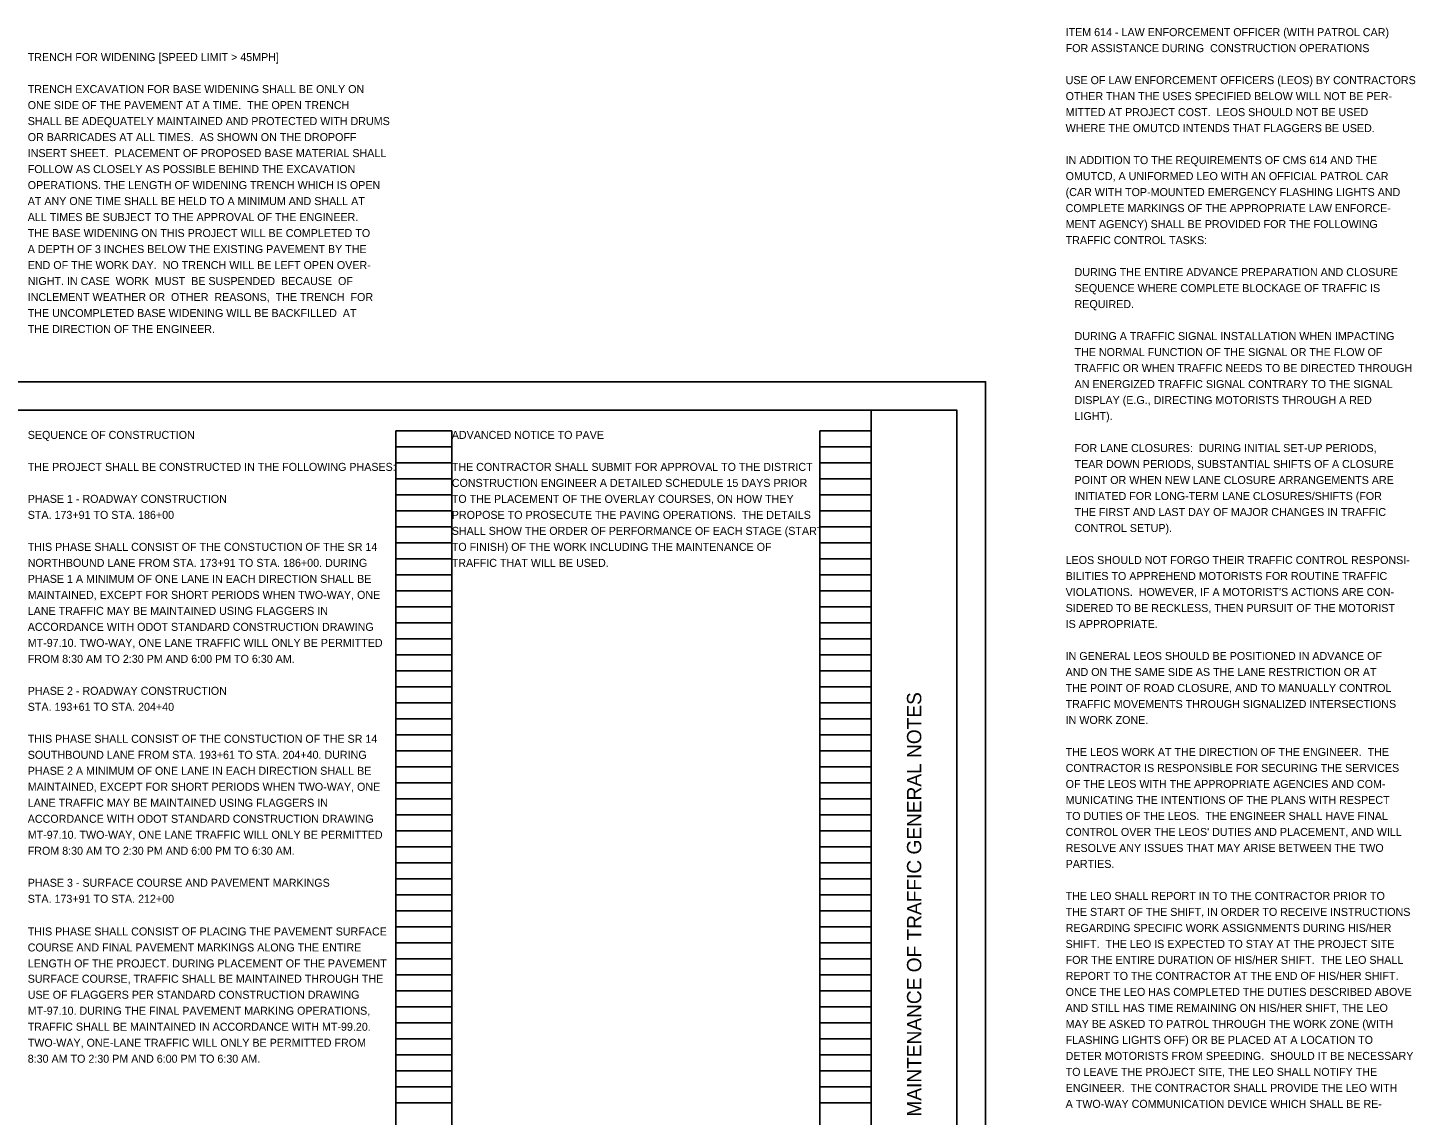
# Model space of a CAD drawing. Extents: x -7.4 to 41.7, y -6.6 to 28.2.
# Drawn here: x 17.24 to 41.52, y 9.16 to 28.2 of the extents above; entities that cross this region are included whole.
import ezdxf

# ---------------------------------------------------------------- set-up
doc = ezdxf.new("R2010")
doc.units = 0
for name, color, linetype in [('SH_Border', 7, 'Continuous'), ('SH_Cut_Line', 7, 'Continuous'), ('SH_Data', 7, 'Continuous'), ('SH_Text', 7, 'Continuous')]:
    doc.layers.add(name, color=color, linetype=linetype)

msp = doc.modelspace()

# ---------------------------------------------------------------- linework, layer by layer
at = {"layer": 'SH_Border'}
msp.add_line((32, 0.5), (32, 21.5), dxfattribs=at)
msp.add_lwpolyline([(1.5, 21.5), (33.5, 21.5), (33.5, 0.5), (1.5, 0.5)], close=True, dxfattribs=at)
at = {"layer": 'SH_Cut_Line'}
msp.add_lwpolyline([(0, 0), (34, 0), (34, 22), (0, 22)], close=True, dxfattribs=at)
at = {"layer": 'SH_Data'}
for p, q in [((23.68, 0.98), (23.68, 21.14)), ((23.68, 21.14), (24.66, 21.14)), ((24.66, 0.98), (24.66, 21.14)), ((31.1, 0.98), (31.1, 21.14)), ((31.1, 21.14), (32, 21.14)), ((32, 0.98), (32, 21.14)), ((23.68, 20.86), (24.66, 20.86)), ((31.1, 20.86), (32, 20.86)), ((23.68, 20.58), (24.66, 20.58)), ((31.1, 20.58), (32, 20.58)), ((23.68, 20.3), (24.66, 20.3)), ((31.1, 20.3), (32, 20.3)), ((23.68, 20.02), (24.66, 20.02)), ((31.1, 20.02), (32, 20.02)), ((23.68, 19.74), (24.66, 19.74)), ((31.1, 19.74), (32, 19.74)), ((23.68, 19.46), (24.66, 19.46)), ((31.1, 19.46), (32, 19.46)), ((23.68, 19.18), (24.66, 19.18)), ((31.1, 19.18), (32, 19.18)), ((23.68, 18.9), (24.66, 18.9)), ((31.1, 18.9), (32, 18.9)), ((23.68, 18.62), (24.66, 18.62)), ((31.1, 18.62), (32, 18.62)), ((23.68, 18.34), (24.66, 18.34)), ((31.1, 18.34), (32, 18.34)), ((23.68, 18.06), (24.66, 18.06)), ((31.1, 18.06), (32, 18.06)), ((23.68, 17.78), (24.66, 17.78)), ((31.1, 17.78), (32, 17.78)), ((23.68, 17.5), (24.66, 17.5)), ((31.1, 17.5), (32, 17.5)), ((23.68, 17.22), (24.66, 17.22)), ((31.1, 17.22), (32, 17.22)), ((23.68, 16.94), (24.66, 16.94)), ((31.1, 16.94), (32, 16.94)), ((23.68, 16.66), (24.66, 16.66)), ((31.1, 16.66), (32, 16.66)), ((23.68, 16.38), (24.66, 16.38)), ((31.1, 16.38), (32, 16.38)), ((23.68, 16.1), (24.66, 16.1)), ((31.1, 16.1), (32, 16.1)), ((23.68, 15.82), (24.66, 15.82)), ((31.1, 15.82), (32, 15.82)), ((23.68, 15.54), (24.66, 15.54)), ((31.1, 15.54), (32, 15.54)), ((23.68, 15.26), (24.66, 15.26)), ((31.1, 15.26), (32, 15.26)), ((23.68, 14.98), (24.66, 14.98)), ((31.1, 14.98), (32, 14.98)), ((23.68, 14.7), (24.66, 14.7)), ((31.1, 14.7), (32, 14.7)), ((23.68, 14.42), (24.66, 14.42)), ((31.1, 14.42), (32, 14.42)), ((23.68, 14.14), (24.66, 14.14)), ((31.1, 14.14), (32, 14.14)), ((23.68, 13.86), (24.66, 13.86)), ((31.1, 13.86), (32, 13.86)), ((23.68, 13.58), (24.66, 13.58)), ((31.1, 13.58), (32, 13.58)), ((23.68, 13.3), (24.66, 13.3)), ((31.1, 13.3), (32, 13.3)), ((23.68, 13.02), (24.66, 13.02)), ((31.1, 13.02), (32, 13.02)), ((23.68, 12.74), (24.66, 12.74)), ((31.1, 12.74), (32, 12.74)), ((23.68, 12.46), (24.66, 12.46)), ((31.1, 12.46), (32, 12.46)), ((23.68, 12.18), (24.66, 12.18)), ((31.1, 12.18), (32, 12.18)), ((23.68, 11.9), (24.66, 11.9)), ((31.1, 11.9), (32, 11.9)), ((23.68, 11.62), (24.66, 11.62)), ((31.1, 11.62), (32, 11.62)), ((23.68, 11.34), (24.66, 11.34)), ((31.1, 11.34), (32, 11.34)), ((23.68, 11.06), (24.66, 11.06)), ((31.1, 11.06), (32, 11.06)), ((23.68, 10.78), (24.66, 10.78)), ((31.1, 10.78), (32, 10.78)), ((23.68, 10.5), (24.66, 10.5)), ((31.1, 10.5), (32, 10.5)), ((23.68, 10.22), (24.66, 10.22)), ((31.1, 10.22), (32, 10.22)), ((23.68, 9.94), (24.66, 9.94)), ((31.1, 9.94), (32, 9.94)), ((23.68, 9.66), (24.66, 9.66)), ((31.1, 9.66), (32, 9.66)), ((23.68, 9.38), (24.66, 9.38)), ((31.1, 9.38), (32, 9.38))]:
    msp.add_line(p, q, dxfattribs=at)

# ---------------------------------------------------------------- texts
msp.add_text('MAINTENANCE OF TRAFFIC GENERAL NOTES', height=0.25, rotation=90, dxfattribs=at).set_placement((32.875, 9.137))
at = {"layer": 'SH_Text'}
for s, p in [('ITEM 614 - LAW ENFORCEMENT OFFICER (WITH PATROL CAR)', (35.401, 28.05)), ('TRENCH FOR WIDENING [SPEED LIMIT > 45MPH]', (17.24, 27.613)), ('FOR ASSISTANCE DURING  CONSTRUCTION OPERATIONS', (35.401, 27.77)), ('TRENCH EXCAVATION FOR BASE WIDENING SHALL BE ONLY ON', (17.24, 27.053)), ('USE OF LAW ENFORCEMENT OFFICERS (LEOS) BY CONTRACTORS', (35.401, 27.21)), ('OTHER THAN THE USES SPECIFIED BELOW WILL NOT BE PER-', (35.401, 26.93)), ('ONE SIDE OF THE PAVEMENT AT A TIME.  THE OPEN TRENCH', (17.24, 26.773)), ('MITTED AT PROJECT COST.  LEOS SHOULD NOT BE USED', (35.401, 26.65)), ('SHALL BE ADEQUATELY MAINTAINED AND PROTECTED WITH DRUMS', (17.24, 26.493)), ('WHERE THE OMUTCD INTENDS THAT FLAGGERS BE USED.', (35.401, 26.37)), ('OR BARRICADES AT ALL TIMES.  AS SHOWN ON THE DROPOFF', (17.24, 26.213)), ('INSERT SHEET.  PLACEMENT OF PROPOSED BASE MATERIAL SHALL', (17.24, 25.933)), ('FOLLOW AS CLOSELY AS POSSIBLE BEHIND THE EXCAVATION', (17.24, 25.653)), ('IN ADDITION TO THE REQUIREMENTS OF CMS 614 AND THE', (35.401, 25.81)), ('OPERATIONS. THE LENGTH OF WIDENING TRENCH WHICH IS OPEN', (17.24, 25.373)), ('OMUTCD, A UNIFORMED LEO WITH AN OFFICIAL PATROL CAR', (35.401, 25.53)), ('(CAR WITH TOP-MOUNTED EMERGENCY FLASHING LIGHTS AND', (35.401, 25.25)), ('AT ANY ONE TIME SHALL BE HELD TO A MINIMUM AND SHALL AT', (17.24, 25.093)), ('COMPLETE MARKINGS OF THE APPROPRIATE LAW ENFORCE-', (35.401, 24.97)), ('ALL TIMES BE SUBJECT TO THE APPROVAL OF THE ENGINEER.', (17.24, 24.813)), ('MENT AGENCY) SHALL BE PROVIDED FOR THE FOLLOWING', (35.401, 24.69)), ('THE BASE WIDENING ON THIS PROJECT WILL BE COMPLETED TO', (17.24, 24.533)), ('TRAFFIC CONTROL TASKS:', (35.401, 24.41)), ('A DEPTH OF 3 INCHES BELOW THE EXISTING PAVEMENT BY THE', (17.24, 24.253)), ('END OF THE WORK DAY.  NO TRENCH WILL BE LEFT OPEN OVER-', (17.24, 23.973)), ('NIGHT. IN CASE  WORK  MUST  BE SUSPENDED  BECAUSE  OF', (17.24, 23.693)), ('   DURING THE ENTIRE ADVANCE PREPARATION AND CLOSURE', (35.401, 23.85)), ('INCLEMENT WEATHER OR  OTHER  REASONS,  THE TRENCH  FOR', (17.24, 23.413)), ('   SEQUENCE WHERE COMPLETE BLOCKAGE OF TRAFFIC IS', (35.401, 23.57)), ('   REQUIRED.', (35.401, 23.29)), ('THE UNCOMPLETED BASE WIDENING WILL BE BACKFILLED  AT', (17.24, 23.133)), ('THE DIRECTION OF THE ENGINEER.', (17.24, 22.853)), ('   DURING A TRAFFIC SIGNAL INSTALLATION WHEN IMPACTING', (35.401, 22.73)), ('   THE NORMAL FUNCTION OF THE SIGNAL OR THE FLOW OF', (35.401, 22.45)), ('   TRAFFIC OR WHEN TRAFFIC NEEDS TO BE DIRECTED THROUGH', (35.401, 22.17)), ('   AN ENERGIZED TRAFFIC SIGNAL CONTRARY TO THE SIGNAL', (35.401, 21.89)), ('   DISPLAY (E.G., DIRECTING MOTORISTS THROUGH A RED', (35.401, 21.61)), ('   LIGHT).', (35.401, 21.33)), ('SEQUENCE OF CONSTRUCTION', (17.24, 21)), ('ADVANCED NOTICE TO PAVE', (24.66, 21)), ('   FOR LANE CLOSURES:  DURING INITIAL SET-UP PERIODS,', (35.401, 20.77)), ('THE PROJECT SHALL BE CONSTRUCTED IN THE FOLLOWING PHASES:', (17.24, 20.44)), ('THE CONTRACTOR SHALL SUBMIT FOR APPROVAL TO THE DISTRICT', (24.66, 20.44)), ('   TEAR DOWN PERIODS, SUBSTANTIAL SHIFTS OF A CLOSURE', (35.401, 20.49)), ('CONSTRUCTION ENGINEER A DETAILED SCHEDULE 15 DAYS PRIOR', (24.66, 20.16)), ('   POINT OR WHEN NEW LANE CLOSURE ARRANGEMENTS ARE', (35.401, 20.21)), ('PHASE 1 - ROADWAY CONSTRUCTION', (17.24, 19.88)), ('TO THE PLACEMENT OF THE OVERLAY COURSES, ON HOW THEY', (24.66, 19.88)), ('   INITIATED FOR LONG-TERM LANE CLOSURES/SHIFTS (FOR', (35.401, 19.93)), ('STA. 173+91 TO STA. 186+00', (17.24, 19.6)), ('PROPOSE TO PROSECUTE THE PAVING OPERATIONS.  THE DETAILS', (24.66, 19.6)), ('   THE FIRST AND LAST DAY OF MAJOR CHANGES IN TRAFFIC', (35.401, 19.65)), ('SHALL SHOW THE ORDER OF PERFORMANCE OF EACH STAGE (START', (24.66, 19.32)), ('   CONTROL SETUP).', (35.401, 19.37)), ('THIS PHASE SHALL CONSIST OF THE CONSTUCTION OF THE SR 14', (17.24, 19.04)), ('TO FINISH) OF THE WORK INCLUDING THE MAINTENANCE OF', (24.66, 19.04)), ('LEOS SHOULD NOT FORGO THEIR TRAFFIC CONTROL RESPONSI-', (35.401, 18.81)), ('NORTHBOUND LANE FROM STA. 173+91 TO STA. 186+00. DURING', (17.24, 18.76)), ('TRAFFIC THAT WILL BE USED.', (24.66, 18.76)), ('PHASE 1 A MINIMUM OF ONE LANE IN EACH DIRECTION SHALL BE ', (17.24, 18.48)), ('BILITIES TO APPREHEND MOTORISTS FOR ROUTINE TRAFFIC', (35.401, 18.53)), ('MAINTAINED, EXCEPT FOR SHORT PERIODS WHEN TWO-WAY, ONE', (17.24, 18.2)), ("VIOLATIONS.  HOWEVER, IF A MOTORIST'S ACTIONS ARE CON-", (35.401, 18.25)), ('LANE TRAFFIC MAY BE MAINTAINED USING FLAGGERS IN ', (17.24, 17.92)), ('SIDERED TO BE RECKLESS, THEN PURSUIT OF THE MOTORIST', (35.401, 17.97)), ('ACCORDANCE WITH ODOT STANDARD CONSTRUCTION DRAWING ', (17.24, 17.64)), ('IS APPROPRIATE.', (35.401, 17.69)), ('MT-97.10. TWO-WAY, ONE LANE TRAFFIC WILL ONLY BE PERMITTED', (17.24, 17.36)), ('IN GENERAL LEOS SHOULD BE POSITIONED IN ADVANCE OF', (35.401, 17.13)), ('FROM 8:30 AM TO 2:30 PM AND 6:00 PM TO 6:30 AM. ', (17.24, 17.08)), ('AND ON THE SAME SIDE AS THE LANE RESTRICTION OR AT', (35.401, 16.85)), ('PHASE 2 - ROADWAY CONSTRUCTION', (17.24, 16.52)), ('THE POINT OF ROAD CLOSURE, AND TO MANUALLY CONTROL', (35.401, 16.57)), ('STA. 193+61 TO STA. 204+40', (17.24, 16.24)), ('TRAFFIC MOVEMENTS THROUGH SIGNALIZED INTERSECTIONS', (35.401, 16.29)), ('IN WORK ZONE.', (35.401, 16.01)), ('THIS PHASE SHALL CONSIST OF THE CONSTUCTION OF THE SR 14', (17.24, 15.68)), ('SOUTHBOUND LANE FROM STA. 193+61 TO STA. 204+40. DURING', (17.24, 15.4)), ('THE LEOS WORK AT THE DIRECTION OF THE ENGINEER.  THE', (35.401, 15.45)), ('CONTRACTOR IS RESPONSIBLE FOR SECURING THE SERVICES', (35.401, 15.17)), ('PHASE 2 A MINIMUM OF ONE LANE IN EACH DIRECTION SHALL BE ', (17.24, 15.12)), ('MAINTAINED, EXCEPT FOR SHORT PERIODS WHEN TWO-WAY, ONE', (17.24, 14.84)), ('OF THE LEOS WITH THE APPROPRIATE AGENCIES AND COM-', (35.401, 14.89)), ('LANE TRAFFIC MAY BE MAINTAINED USING FLAGGERS IN ', (17.24, 14.56)), ('MUNICATING THE INTENTIONS OF THE PLANS WITH RESPECT', (35.401, 14.61)), ('ACCORDANCE WITH ODOT STANDARD CONSTRUCTION DRAWING ', (17.24, 14.28)), ('TO DUTIES OF THE LEOS.  THE ENGINEER SHALL HAVE FINAL', (35.401, 14.33)), ('MT-97.10. TWO-WAY, ONE LANE TRAFFIC WILL ONLY BE PERMITTED', (17.24, 14)), ("CONTROL OVER THE LEOS' DUTIES AND PLACEMENT, AND WILL", (35.401, 14.05)), ('FROM 8:30 AM TO 2:30 PM AND 6:00 PM TO 6:30 AM. ', (17.24, 13.72)), ('RESOLVE ANY ISSUES THAT MAY ARISE BETWEEN THE TWO', (35.401, 13.77)), ('PARTIES.', (35.401, 13.49)), ('PHASE 3 - SURFACE COURSE AND PAVEMENT MARKINGS', (17.24, 13.16)), ('STA. 173+91 TO STA. 212+00', (17.24, 12.88)), ('THE LEO SHALL REPORT IN TO THE CONTRACTOR PRIOR TO', (35.401, 12.93)), ('THE START OF THE SHIFT, IN ORDER TO RECEIVE INSTRUCTIONS', (35.401, 12.65)), ('THIS PHASE SHALL CONSIST OF PLACING THE PAVEMENT SURFACE', (17.24, 12.308)), ('REGARDING SPECIFIC WORK ASSIGNMENTS DURING HIS/HER', (35.401, 12.37)), ('COURSE AND FINAL PAVEMENT MARKINGS ALONG THE ENTIRE', (17.24, 12.028)), ('SHIFT.  THE LEO IS EXPECTED TO STAY AT THE PROJECT SITE', (35.401, 12.09)), ('FOR THE ENTIRE DURATION OF HIS/HER SHIFT.  THE LEO SHALL', (35.401, 11.81)), ('LENGTH OF THE PROJECT. DURING PLACEMENT OF THE PAVEMENT', (17.24, 11.748)), ('REPORT TO THE CONTRACTOR AT THE END OF HIS/HER SHIFT.', (35.401, 11.53)), ('SURFACE COURSE, TRAFFIC SHALL BE MAINTAINED THROUGH THE', (17.24, 11.48)), ('USE OF FLAGGERS PER STANDARD CONSTRUCTION DRAWING ', (17.24, 11.2)), ('ONCE THE LEO HAS COMPLETED THE DUTIES DESCRIBED ABOVE', (35.401, 11.25)), ('MT-97.10. DURING THE FINAL PAVEMENT MARKING OPERATIONS, ', (17.24, 10.92)), ('AND STILL HAS TIME REMAINING ON HIS/HER SHIFT, THE LEO', (35.401, 10.97)), ('TRAFFIC SHALL BE MAINTAINED IN ACCORDANCE WITH MT-99.20. ', (17.24, 10.64)), ('MAY BE ASKED TO PATROL THROUGH THE WORK ZONE (WITH', (35.401, 10.69)), ('TWO-WAY, ONE-LANE TRAFFIC WILL ONLY BE PERMITTED FROM', (17.24, 10.36)), ('FLASHING LIGHTS OFF) OR BE PLACED AT A LOCATION TO', (35.401, 10.41)), ('8:30 AM TO 2:30 PM AND 6:00 PM TO 6:30 AM. ', (17.24, 10.08)), ('DETER MOTORISTS FROM SPEEDING.  SHOULD IT BE NECESSARY', (35.401, 10.13)), ('TO LEAVE THE PROJECT SITE, THE LEO SHALL NOTIFY THE', (35.401, 9.85)), ('ENGINEER.  THE CONTRACTOR SHALL PROVIDE THE LEO WITH', (35.401, 9.57)), ('A TWO-WAY COMMUNICATION DEVICE WHICH SHALL BE RE-', (35.401, 9.29))]:
    msp.add_text(s, height=0.14, dxfattribs=at).set_placement(p)

doc.saveas('drawing.dxf')
